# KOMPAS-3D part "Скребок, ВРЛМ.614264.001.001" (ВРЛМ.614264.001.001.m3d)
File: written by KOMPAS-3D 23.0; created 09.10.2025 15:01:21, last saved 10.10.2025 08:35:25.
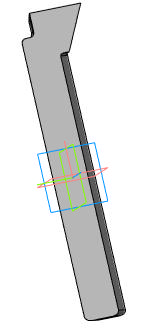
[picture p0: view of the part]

Document properties: Автор: EmelyanenkoEY; Полное имя файла: ВРЛМ.614264.001.001.cdw

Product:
- Part/product: Скребок  | designation ВРЛМ.614264.001.001
    Материал: Сталь 03Х17Н14М3 ГОСТ 5632-2014 (density 8000 kg/m3)
    Масса: 0.518086
    Форматы листов документа: A3

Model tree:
1. Эскиз:1
2. Элемент выдавливания:1
     Расстояние 1 = 8
3. Эскиз:3  (with: Элемент выдавливания:1)
4. Элемент выдавливания:3
     Расстояние 2 = 224
5. Фаска:3  (with: Элемент выдавливания:1)
     Угол = 45; Длина 1 = 8; Длина 2 = 8
6. Эскиз:5  (with: Элемент выдавливания:1)
7. Элемент выдавливания:5
     Расстояние 2 = 45
8. Эскиз:6  (with: Элемент выдавливания:1, Элемент выдавливания:3)
9. Элемент выдавливания:6
10. Скругление:8  (with: Фаска:3, Элемент выдавливания:3)
     Радиус = 4
11. Скругление:9  (with: Элемент выдавливания:3)
     Радиус = 2
12. Скругление:10  (with: Элемент выдавливания:1)
     Радиус = 4
13. Эскиз:7  (with: Элемент выдавливания:1)
14. Элемент выдавливания:7  (labels: Сталь 03Х17Н14М3 ГОСТ 5632-2014; BOSimple***Material:eb0a4e4c-f881-4f25-af2f-9f38547546d4)
     Расстояние 2 = 10

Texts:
  ВРЛМ.614264.001.001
